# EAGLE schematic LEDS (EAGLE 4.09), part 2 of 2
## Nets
LED2.27: LED0.27.P$A LED1.27.P$A LED2.27.P$A LED3.27.P$A LED4.27.P$A LED5.27.P$A LED6.27.P$A LED7.27.P$A LED8.27.P$A LED9.27.P$A LED10.27.P$A LED11.27.P$A LED12.27.P$A LED13.27.P$A LED14.27.P$A LED15.27.P$A LED16.27.P$A LED17.27.P$A LED18.27.P$A LED19.27.P$A LED20.27.P$A LED21.27.P$A X27.P$
N$X.0: LED0.0.P$A LED1.0.P$A LED2.0.P$A LED3.0.P$A LED4.0.P$A LED5.0.P$A LED6.0.P$A LED7.0.P$A LED8.0.P$A LED9.0.P$A LED10.0.P$A LED11.0.P$A LED12.0.P$A LED13.0.P$A LED14.0.P$A LED15.0.P$A LED16.0.P$A LED17.0.P$A LED18.0.P$A LED19.0.P$A LED20.0.P$A LED21.0.P$A X0.P$
N$X.1: LED0.1.P$A LED1.1.P$A LED2.1.P$A LED3.1.P$A LED4.1.P$A LED5.1.P$A LED6.1.P$A LED7.1.P$A LED8.1.P$A LED9.1.P$A LED10.1.P$A LED11.1.P$A LED12.1.P$A LED13.1.P$A LED14.1.P$A LED15.1.P$A LED16.1.P$A LED17.1.P$A LED18.1.P$A LED19.1.P$A LED20.1.P$A LED21.1.P$A X1.P$
N$X.2: LED0.2.P$A LED1.2.P$A LED2.2.P$A LED3.2.P$A LED4.2.P$A LED5.2.P$A LED6.2.P$A LED7.2.P$A LED8.2.P$A LED9.2.P$A LED10.2.P$A LED11.2.P$A LED12.2.P$A LED13.2.P$A LED14.2.P$A LED15.2.P$A LED16.2.P$A LED17.2.P$A LED18.2.P$A LED19.2.P$A LED20.2.P$A LED21.2.P$A X2.P$
N$X.3: LED0.3.P$A LED1.3.P$A LED2.3.P$A LED3.3.P$A LED4.3.P$A LED5.3.P$A LED6.3.P$A LED7.3.P$A LED8.3.P$A LED9.3.P$A LED10.3.P$A LED11.3.P$A LED12.3.P$A LED13.3.P$A LED14.3.P$A LED15.3.P$A LED16.3.P$A LED17.3.P$A LED18.3.P$A LED19.3.P$A LED20.3.P$A LED21.3.P$A X3.P$
N$X.4: LED0.4.P$A LED1.4.P$A LED2.4.P$A LED3.4.P$A LED4.4.P$A LED5.4.P$A LED6.4.P$A LED7.4.P$A LED8.4.P$A LED9.4.P$A LED10.4.P$A LED11.4.P$A LED12.4.P$A LED13.4.P$A LED14.4.P$A LED15.4.P$A LED16.4.P$A LED17.4.P$A LED18.4.P$A LED19.4.P$A LED20.4.P$A LED21.4.P$A X4.P$
N$X.5: LED0.5.P$A LED1.5.P$A LED2.5.P$A LED3.5.P$A LED4.5.P$A LED5.5.P$A LED6.5.P$A LED7.5.P$A LED8.5.P$A LED9.5.P$A LED10.5.P$A LED11.5.P$A LED12.5.P$A LED13.5.P$A LED14.5.P$A LED15.5.P$A LED16.5.P$A LED17.5.P$A LED18.5.P$A LED19.5.P$A LED20.5.P$A LED21.5.P$A X5.P$
N$X.6: LED0.6.P$A LED1.6.P$A LED2.6.P$A LED3.6.P$A LED4.6.P$A LED5.6.P$A LED6.6.P$A LED7.6.P$A LED8.6.P$A LED9.6.P$A LED10.6.P$A LED11.6.P$A LED12.6.P$A LED13.6.P$A LED14.6.P$A LED15.6.P$A LED16.6.P$A LED17.6.P$A LED18.6.P$A LED19.6.P$A LED20.6.P$A LED21.6.P$A X6.P$
N$X.7: LED0.7.P$A LED1.7.P$A LED2.7.P$A LED3.7.P$A LED4.7.P$A LED5.7.P$A LED6.7.P$A LED7.7.P$A LED8.7.P$A LED9.7.P$A LED10.7.P$A LED11.7.P$A LED12.7.P$A LED13.7.P$A LED14.7.P$A LED15.7.P$A LED16.7.P$A LED17.7.P$A LED18.7.P$A LED19.7.P$A LED20.7.P$A LED21.7.P$A X7.P$
N$X.8: LED0.8.P$A LED1.8.P$A LED2.8.P$A LED3.8.P$A LED4.8.P$A LED5.8.P$A LED6.8.P$A LED7.8.P$A LED8.8.P$A LED9.8.P$A LED10.8.P$A LED11.8.P$A LED12.8.P$A LED13.8.P$A LED14.8.P$A LED15.8.P$A LED16.8.P$A LED17.8.P$A LED18.8.P$A LED19.8.P$A LED20.8.P$A LED21.8.P$A X8.P$
N$X.9: LED0.9.P$A LED1.9.P$A LED2.9.P$A LED3.9.P$A LED4.9.P$A LED5.9.P$A LED6.9.P$A LED7.9.P$A LED8.9.P$A LED9.9.P$A LED10.9.P$A LED11.9.P$A LED12.9.P$A LED13.9.P$A LED14.9.P$A LED15.9.P$A LED16.9.P$A LED17.9.P$A LED18.9.P$A LED19.9.P$A LED20.9.P$A LED21.9.P$A X9.P$
N$X.10: LED0.10.P$A LED1.10.P$A LED2.10.P$A LED3.10.P$A LED4.10.P$A LED5.10.P$A LED6.10.P$A LED7.10.P$A LED8.10.P$A LED9.10.P$A LED10.10.P$A LED11.10.P$A LED12.10.P$A LED13.10.P$A LED14.10.P$A LED15.10.P$A LED16.10.P$A LED17.10.P$A LED18.10.P$A LED19.10.P$A LED20.10.P$A LED21.10.P$A X10.P$
N$X.11: LED0.11.P$A LED1.11.P$A LED2.11.P$A LED3.11.P$A LED4.11.P$A LED5.11.P$A LED6.11.P$A LED7.11.P$A LED8.11.P$A LED9.11.P$A LED10.11.P$A LED11.11.P$A LED12.11.P$A LED13.11.P$A LED14.11.P$A LED15.11.P$A LED16.11.P$A LED17.11.P$A LED18.11.P$A LED19.11.P$A LED20.11.P$A LED21.11.P$A X11.P$
N$X.12: LED0.12.P$A LED1.12.P$A LED2.12.P$A LED3.12.P$A LED4.12.P$A LED5.12.P$A LED6.12.P$A LED7.12.P$A LED8.12.P$A LED9.12.P$A LED10.12.P$A LED11.12.P$A LED12.12.P$A LED13.12.P$A LED14.12.P$A LED15.12.P$A LED16.12.P$A LED17.12.P$A LED18.12.P$A LED19.12.P$A LED20.12.P$A LED21.12.P$A X12.P$
N$X.13: LED0.13.P$A LED1.13.P$A LED2.13.P$A LED3.13.P$A LED4.13.P$A LED5.13.P$A LED6.13.P$A LED7.13.P$A LED8.13.P$A LED9.13.P$A LED10.13.P$A LED11.13.P$A LED12.13.P$A LED13.13.P$A LED14.13.P$A LED15.13.P$A LED16.13.P$A LED17.13.P$A LED18.13.P$A LED19.13.P$A LED20.13.P$A LED21.13.P$A X13.P$
N$X.14: LED0.14.P$A LED1.14.P$A LED2.14.P$A LED3.14.P$A LED4.14.P$A LED5.14.P$A LED6.14.P$A LED7.14.P$A LED8.14.P$A LED9.14.P$A LED10.14.P$A LED11.14.P$A LED12.14.P$A LED13.14.P$A LED14.14.P$A LED15.14.P$A LED16.14.P$A LED17.14.P$A LED18.14.P$A LED19.14.P$A LED20.14.P$A LED21.14.P$A X14.P$
N$X.15: LED0.15.P$A LED1.15.P$A LED2.15.P$A LED3.15.P$A LED4.15.P$A LED5.15.P$A LED6.15.P$A LED7.15.P$A LED8.15.P$A LED9.15.P$A LED10.15.P$A LED11.15.P$A LED12.15.P$A LED13.15.P$A LED14.15.P$A LED15.15.P$A LED16.15.P$A LED17.15.P$A LED18.15.P$A LED19.15.P$A LED20.15.P$A LED21.15.P$A X15.P$
N$X.16: LED0.16.P$A LED1.16.P$A LED2.16.P$A LED3.16.P$A LED4.16.P$A LED5.16.P$A LED6.16.P$A LED7.16.P$A LED8.16.P$A LED9.16.P$A LED10.16.P$A LED11.16.P$A LED12.16.P$A LED13.16.P$A LED14.16.P$A LED15.16.P$A LED16.16.P$A LED17.16.P$A LED18.16.P$A LED19.16.P$A LED20.16.P$A LED21.16.P$A X16.P$
N$X.17: LED0.17.P$A LED1.17.P$A LED2.17.P$A LED3.17.P$A LED4.17.P$A LED5.17.P$A LED6.17.P$A LED7.17.P$A LED8.17.P$A LED9.17.P$A LED10.17.P$A LED11.17.P$A LED12.17.P$A LED13.17.P$A LED14.17.P$A LED15.17.P$A LED16.17.P$A LED17.17.P$A LED18.17.P$A LED19.17.P$A LED20.17.P$A LED21.17.P$A X17.P$
N$X.18: LED0.18.P$A LED1.18.P$A LED2.18.P$A LED3.18.P$A LED4.18.P$A LED5.18.P$A LED6.18.P$A LED7.18.P$A LED8.18.P$A LED9.18.P$A LED10.18.P$A LED11.18.P$A LED12.18.P$A LED13.18.P$A LED14.18.P$A LED15.18.P$A LED16.18.P$A LED17.18.P$A LED18.18.P$A LED19.18.P$A LED20.18.P$A LED21.18.P$A X18.P$
N$X.19: LED0.19.P$A LED1.19.P$A LED2.19.P$A LED3.19.P$A LED4.19.P$A LED5.19.P$A LED6.19.P$A LED7.19.P$A LED8.19.P$A LED9.19.P$A LED10.19.P$A LED11.19.P$A LED12.19.P$A LED13.19.P$A LED14.19.P$A LED15.19.P$A LED16.19.P$A LED17.19.P$A LED18.19.P$A LED19.19.P$A LED20.19.P$A LED21.19.P$A X19.P$
N$X.20: LED0.20.P$A LED1.20.P$A LED2.20.P$A LED3.20.P$A LED4.20.P$A LED5.20.P$A LED6.20.P$A LED7.20.P$A LED8.20.P$A LED9.20.P$A LED10.20.P$A LED11.20.P$A LED12.20.P$A LED13.20.P$A LED14.20.P$A LED15.20.P$A LED16.20.P$A LED17.20.P$A LED18.20.P$A LED19.20.P$A LED20.20.P$A LED21.20.P$A X20.P$
N$X.21: LED0.21.P$A LED1.21.P$A LED2.21.P$A LED3.21.P$A LED4.21.P$A LED5.21.P$A LED6.21.P$A LED7.21.P$A LED8.21.P$A LED9.21.P$A LED10.21.P$A LED11.21.P$A LED12.21.P$A LED13.21.P$A LED14.21.P$A LED15.21.P$A LED16.21.P$A LED17.21.P$A LED18.21.P$A LED19.21.P$A LED20.21.P$A LED21.21.P$A X21.P$
N$X.22: LED0.22.P$A LED1.22.P$A LED2.22.P$A LED3.22.P$A LED4.22.P$A LED5.22.P$A LED6.22.P$A LED7.22.P$A LED8.22.P$A LED9.22.P$A LED10.22.P$A LED11.22.P$A LED12.22.P$A LED13.22.P$A LED14.22.P$A LED15.22.P$A LED16.22.P$A LED17.22.P$A LED18.22.P$A LED19.22.P$A LED20.22.P$A LED21.22.P$A X22.P$
N$X.23: LED0.23.P$A LED1.23.P$A LED2.23.P$A LED3.23.P$A LED4.23.P$A LED5.23.P$A LED6.23.P$A LED7.23.P$A LED8.23.P$A LED9.23.P$A LED10.23.P$A LED11.23.P$A LED12.23.P$A LED13.23.P$A LED14.23.P$A LED15.23.P$A LED16.23.P$A LED17.23.P$A LED18.23.P$A LED19.23.P$A LED20.23.P$A LED21.23.P$A X23.P$
N$X.24: LED0.24.P$A LED1.24.P$A LED2.24.P$A LED3.24.P$A LED4.24.P$A LED5.24.P$A LED6.24.P$A LED7.24.P$A LED8.24.P$A LED9.24.P$A LED10.24.P$A LED11.24.P$A LED12.24.P$A LED13.24.P$A LED14.24.P$A LED15.24.P$A LED16.24.P$A LED17.24.P$A LED18.24.P$A LED19.24.P$A LED20.24.P$A LED21.24.P$A X24.P$
N$X.25: LED0.25.P$A LED1.25.P$A LED2.25.P$A LED3.25.P$A LED4.25.P$A LED5.25.P$A LED6.25.P$A LED7.25.P$A LED8.25.P$A LED9.25.P$A LED10.25.P$A LED11.25.P$A LED12.25.P$A LED13.25.P$A LED14.25.P$A LED15.25.P$A LED16.25.P$A LED17.25.P$A LED18.25.P$A LED19.25.P$A LED20.25.P$A LED21.25.P$A X25.P$
N$X.26: LED0.26.P$A LED1.26.P$A LED2.26.P$A LED3.26.P$A LED4.26.P$A LED5.26.P$A LED6.26.P$A LED7.26.P$A LED8.26.P$A LED9.26.P$A LED10.26.P$A LED11.26.P$A LED12.26.P$A LED13.26.P$A LED14.26.P$A LED15.26.P$A LED16.26.P$A LED17.26.P$A LED18.26.P$A LED19.26.P$A LED20.26.P$A LED21.26.P$A X26.P$
N$X.28: LED0.28.P$A LED1.28.P$A LED2.28.P$A LED3.28.P$A LED4.28.P$A LED5.28.P$A LED6.28.P$A LED7.28.P$A LED8.28.P$A LED9.28.P$A LED10.28.P$A LED11.28.P$A LED12.28.P$A LED13.28.P$A LED14.28.P$A LED15.28.P$A LED16.28.P$A LED17.28.P$A LED18.28.P$A LED19.28.P$A LED20.28.P$A LED21.28.P$A X28.P$
N$X.29: LED0.29.P$A LED1.29.P$A LED2.29.P$A LED3.29.P$A LED4.29.P$A LED5.29.P$A LED6.29.P$A LED7.29.P$A LED8.29.P$A LED9.29.P$A LED10.29.P$A LED11.29.P$A LED12.29.P$A LED13.29.P$A LED14.29.P$A LED15.29.P$A LED16.29.P$A LED17.29.P$A LED18.29.P$A LED19.29.P$A LED20.29.P$A LED21.29.P$A X29.P$
N$X.30: LED0.30.P$A LED1.30.P$A LED2.30.P$A LED3.30.P$A LED4.30.P$A LED5.30.P$A LED6.30.P$A LED7.30.P$A LED8.30.P$A LED9.30.P$A LED10.30.P$A LED11.30.P$A LED12.30.P$A LED13.30.P$A LED14.30.P$A LED15.30.P$A LED16.30.P$A LED17.30.P$A LED18.30.P$A LED19.30.P$A LED20.30.P$A LED21.30.P$A X30.P$
N$X.31: LED0.31.P$A LED1.31.P$A LED2.31.P$A LED3.31.P$A LED4.31.P$A LED5.31.P$A LED6.31.P$A LED7.31.P$A LED8.31.P$A LED9.31.P$A LED10.31.P$A LED11.31.P$A LED12.31.P$A LED13.31.P$A LED14.31.P$A LED15.31.P$A LED16.31.P$A LED17.31.P$A LED18.31.P$A LED19.31.P$A LED20.31.P$A LED21.31.P$A X31.P$
N$X.32: LED0.32.P$A LED1.32.P$A LED2.32.P$A LED3.32.P$A LED4.32.P$A LED5.32.P$A LED6.32.P$A LED7.32.P$A LED8.32.P$A LED9.32.P$A LED10.32.P$A LED11.32.P$A LED12.32.P$A LED13.32.P$A LED14.32.P$A LED15.32.P$A LED16.32.P$A LED17.32.P$A LED18.32.P$A LED19.32.P$A LED20.32.P$A LED21.32.P$A X32.P$
N$X.33: LED0.33.P$A LED1.33.P$A LED2.33.P$A LED3.33.P$A LED4.33.P$A LED5.33.P$A LED6.33.P$A LED7.33.P$A LED8.33.P$A LED9.33.P$A LED10.33.P$A LED11.33.P$A LED12.33.P$A LED13.33.P$A LED14.33.P$A LED15.33.P$A LED16.33.P$A LED17.33.P$A LED18.33.P$A LED19.33.P$A LED20.33.P$A LED21.33.P$A X33.P$
N$X.34: LED0.34.P$A LED1.34.P$A LED2.34.P$A LED3.34.P$A LED4.34.P$A LED5.34.P$A LED6.34.P$A LED7.34.P$A LED8.34.P$A LED9.34.P$A LED10.34.P$A LED11.34.P$A LED12.34.P$A LED13.34.P$A LED14.34.P$A LED15.34.P$A LED16.34.P$A LED17.34.P$A LED18.34.P$A LED19.34.P$A LED20.34.P$A LED21.34.P$A X34.P$
N$X.35: LED0.35.P$A LED1.35.P$A LED2.35.P$A LED3.35.P$A LED4.35.P$A LED5.35.P$A LED6.35.P$A LED7.35.P$A LED8.35.P$A LED9.35.P$A LED10.35.P$A LED11.35.P$A LED12.35.P$A LED13.35.P$A LED14.35.P$A LED15.35.P$A LED16.35.P$A LED17.35.P$A LED18.35.P$A LED19.35.P$A LED20.35.P$A LED21.35.P$A X35.P$
N$X.36: LED0.36.P$A LED1.36.P$A LED2.36.P$A LED3.36.P$A LED4.36.P$A LED5.36.P$A LED6.36.P$A LED7.36.P$A LED8.36.P$A LED9.36.P$A LED10.36.P$A LED11.36.P$A LED12.36.P$A LED13.36.P$A LED14.36.P$A LED15.36.P$A LED16.36.P$A LED17.36.P$A LED18.36.P$A LED19.36.P$A LED20.36.P$A LED21.36.P$A X36.P$
N$X.37: LED0.37.P$A LED1.37.P$A LED2.37.P$A LED3.37.P$A LED4.37.P$A LED5.37.P$A LED6.37.P$A LED7.37.P$A LED8.37.P$A LED9.37.P$A LED10.37.P$A LED11.37.P$A LED12.37.P$A LED13.37.P$A LED14.37.P$A LED15.37.P$A LED16.37.P$A LED17.37.P$A LED18.37.P$A LED19.37.P$A LED20.37.P$A LED21.37.P$A X37.P$
N$X.38: LED0.38.P$A LED1.38.P$A LED2.38.P$A LED3.38.P$A LED4.38.P$A LED5.38.P$A LED6.38.P$A LED7.38.P$A LED8.38.P$A LED9.38.P$A LED10.38.P$A LED11.38.P$A LED12.38.P$A LED13.38.P$A LED14.38.P$A LED15.38.P$A LED16.38.P$A LED17.38.P$A LED18.38.P$A LED19.38.P$A LED20.38.P$A LED21.38.P$A X38.P$
N$X.39: LED0.39.P$A LED1.39.P$A LED2.39.P$A LED3.39.P$A LED4.39.P$A LED5.39.P$A LED6.39.P$A LED7.39.P$A LED8.39.P$A LED9.39.P$A LED10.39.P$A LED11.39.P$A LED12.39.P$A LED13.39.P$A LED14.39.P$A LED15.39.P$A LED16.39.P$A LED17.39.P$A LED18.39.P$A LED19.39.P$A LED20.39.P$A LED21.39.P$A X39.P$
N$X.40: LED0.40.P$A LED1.40.P$A LED2.40.P$A LED3.40.P$A LED4.40.P$A LED5.40.P$A LED6.40.P$A LED7.40.P$A LED8.40.P$A LED9.40.P$A LED10.40.P$A LED11.40.P$A LED12.40.P$A LED13.40.P$A LED14.40.P$A LED15.40.P$A LED16.40.P$A LED17.40.P$A LED18.40.P$A LED19.40.P$A LED20.40.P$A LED21.40.P$A X40.P$
N$X.41: LED0.41.P$A LED1.41.P$A LED2.41.P$A LED3.41.P$A LED4.41.P$A LED5.41.P$A LED6.41.P$A LED7.41.P$A LED8.41.P$A LED9.41.P$A LED10.41.P$A LED11.41.P$A LED12.41.P$A LED13.41.P$A LED14.41.P$A LED15.41.P$A LED16.41.P$A LED17.41.P$A LED18.41.P$A LED19.41.P$A LED20.41.P$A LED21.41.P$A X41.P$
N$X.42: LED0.42.P$A LED1.42.P$A LED2.42.P$A LED3.42.P$A LED4.42.P$A LED5.42.P$A LED6.42.P$A LED7.42.P$A LED8.42.P$A LED9.42.P$A LED10.42.P$A LED11.42.P$A LED12.42.P$A LED13.42.P$A LED14.42.P$A LED15.42.P$A LED16.42.P$A LED17.42.P$A LED18.42.P$A LED19.42.P$A LED20.42.P$A LED21.42.P$A X42.P$
N$X.43: LED0.43.P$A LED1.43.P$A LED2.43.P$A LED3.43.P$A LED4.43.P$A LED5.43.P$A LED6.43.P$A LED7.43.P$A LED8.43.P$A LED9.43.P$A LED10.43.P$A LED11.43.P$A LED12.43.P$A LED13.43.P$A LED14.43.P$A LED15.43.P$A LED16.43.P$A LED17.43.P$A LED18.43.P$A LED19.43.P$A LED20.43.P$A LED21.43.P$A X43.P$
N$X.44: LED0.44.P$A LED1.44.P$A LED2.44.P$A LED3.44.P$A LED4.44.P$A LED5.44.P$A LED6.44.P$A LED7.44.P$A LED8.44.P$A LED9.44.P$A LED10.44.P$A LED11.44.P$A LED12.44.P$A LED13.44.P$A LED14.44.P$A LED15.44.P$A LED16.44.P$A LED17.44.P$A LED18.44.P$A LED19.44.P$A LED20.44.P$A LED21.44.P$A X44.P$
N$X.45: LED0.45.P$A LED1.45.P$A LED2.45.P$A LED3.45.P$A LED4.45.P$A LED5.45.P$A LED6.45.P$A LED7.45.P$A LED8.45.P$A LED9.45.P$A LED10.45.P$A LED11.45.P$A LED12.45.P$A LED13.45.P$A LED14.45.P$A LED15.45.P$A LED16.45.P$A LED17.45.P$A LED18.45.P$A LED19.45.P$A LED20.45.P$A LED21.45.P$A X45.P$
N$X.46: LED0.46.P$A LED1.46.P$A LED2.46.P$A LED3.46.P$A LED4.46.P$A LED5.46.P$A LED6.46.P$A LED7.46.P$A LED8.46.P$A LED9.46.P$A LED10.46.P$A LED11.46.P$A LED12.46.P$A LED13.46.P$A LED14.46.P$A LED15.46.P$A LED16.46.P$A LED17.46.P$A LED18.46.P$A LED19.46.P$A LED20.46.P$A LED21.46.P$A X46.P$
N$X.47: LED0.47.P$A LED1.47.P$A LED2.47.P$A LED3.47.P$A LED4.47.P$A LED5.47.P$A LED6.47.P$A LED7.47.P$A LED8.47.P$A LED9.47.P$A LED10.47.P$A LED11.47.P$A LED12.47.P$A LED13.47.P$A LED14.47.P$A LED15.47.P$A LED16.47.P$A LED17.47.P$A LED18.47.P$A LED19.47.P$A LED20.47.P$A LED21.47.P$A X47.P$
N$X.48: LED0.48.P$A LED1.48.P$A LED2.48.P$A LED3.48.P$A LED4.48.P$A LED5.48.P$A LED6.48.P$A LED7.48.P$A LED8.48.P$A LED9.48.P$A LED10.48.P$A LED11.48.P$A LED12.48.P$A LED13.48.P$A LED14.48.P$A LED15.48.P$A LED16.48.P$A LED17.48.P$A LED18.48.P$A LED19.48.P$A LED20.48.P$A LED21.48.P$A X48.P$
N$X.49: LED0.49.P$A LED1.49.P$A LED2.49.P$A LED3.49.P$A LED4.49.P$A LED5.49.P$A LED6.49.P$A LED7.49.P$A LED8.49.P$A LED9.49.P$A LED10.49.P$A LED11.49.P$A LED12.49.P$A LED13.49.P$A LED14.49.P$A LED15.49.P$A LED16.49.P$A LED17.49.P$A LED18.49.P$A LED19.49.P$A LED20.49.P$A LED21.49.P$A X49.P$
N$X.50: LED0.50.P$A LED1.50.P$A LED2.50.P$A LED3.50.P$A LED4.50.P$A LED5.50.P$A LED6.50.P$A LED7.50.P$A LED8.50.P$A LED9.50.P$A LED10.50.P$A LED11.50.P$A LED12.50.P$A LED13.50.P$A LED14.50.P$A LED15.50.P$A LED16.50.P$A LED17.50.P$A LED18.50.P$A LED19.50.P$A LED20.50.P$A LED21.50.P$A X50.P$
N$X.51: LED0.51.P$A LED1.51.P$A LED2.51.P$A LED3.51.P$A LED4.51.P$A LED5.51.P$A LED6.51.P$A LED7.51.P$A LED8.51.P$A LED9.51.P$A LED10.51.P$A LED11.51.P$A LED12.51.P$A LED13.51.P$A LED14.51.P$A LED15.51.P$A LED16.51.P$A LED17.51.P$A LED18.51.P$A LED19.51.P$A LED20.51.P$A LED21.51.P$A X51.P$
N$X.52: LED0.52.P$A LED1.52.P$A LED2.52.P$A LED3.52.P$A LED4.52.P$A LED5.52.P$A LED6.52.P$A LED7.52.P$A LED8.52.P$A LED9.52.P$A LED10.52.P$A LED11.52.P$A LED12.52.P$A LED13.52.P$A LED14.52.P$A LED15.52.P$A LED16.52.P$A LED17.52.P$A LED18.52.P$A LED19.52.P$A LED20.52.P$A LED21.52.P$A X52.P$
N$X.53: LED0.53.P$A LED1.53.P$A LED2.53.P$A LED3.53.P$A LED4.53.P$A LED5.53.P$A LED6.53.P$A LED7.53.P$A LED8.53.P$A LED9.53.P$A LED10.53.P$A LED11.53.P$A LED12.53.P$A LED13.53.P$A LED14.53.P$A LED15.53.P$A LED16.53.P$A LED17.53.P$A LED18.53.P$A LED19.53.P$A LED20.53.P$A LED21.53.P$A X53.P$
N$X.54: LED0.54.P$A LED1.54.P$A LED2.54.P$A LED3.54.P$A LED4.54.P$A LED5.54.P$A LED6.54.P$A LED7.54.P$A LED8.54.P$A LED9.54.P$A LED10.54.P$A LED11.54.P$A LED12.54.P$A LED13.54.P$A LED14.54.P$A LED15.54.P$A LED16.54.P$A LED17.54.P$A LED18.54.P$A LED19.54.P$A LED20.54.P$A LED21.54.P$A X54.P$
N$X.55: LED0.55.P$A LED1.55.P$A LED2.55.P$A LED3.55.P$A LED4.55.P$A LED5.55.P$A LED6.55.P$A LED7.55.P$A LED8.55.P$A LED9.55.P$A LED10.55.P$A LED11.55.P$A LED12.55.P$A LED13.55.P$A LED14.55.P$A LED15.55.P$A LED16.55.P$A LED17.55.P$A LED18.55.P$A LED19.55.P$A LED20.55.P$A LED21.55.P$A X55.P$
N$X.56: LED0.56.P$A LED1.56.P$A LED2.56.P$A LED3.56.P$A LED4.56.P$A LED5.56.P$A LED6.56.P$A LED7.56.P$A LED8.56.P$A LED9.56.P$A LED10.56.P$A LED11.56.P$A LED12.56.P$A LED13.56.P$A LED14.56.P$A LED15.56.P$A LED16.56.P$A LED17.56.P$A LED18.56.P$A LED19.56.P$A LED20.56.P$A LED21.56.P$A X56.P$
N$X.57: LED0.57.P$A LED1.57.P$A LED2.57.P$A LED3.57.P$A LED4.57.P$A LED5.57.P$A LED6.57.P$A LED7.57.P$A LED8.57.P$A LED9.57.P$A LED10.57.P$A LED11.57.P$A LED12.57.P$A LED13.57.P$A LED14.57.P$A LED15.57.P$A LED16.57.P$A LED17.57.P$A LED18.57.P$A LED19.57.P$A LED20.57.P$A LED21.57.P$A X57.P$
N$X.58: LED0.58.P$A LED1.58.P$A LED2.58.P$A LED3.58.P$A LED4.58.P$A LED5.58.P$A LED6.58.P$A LED7.58.P$A LED8.58.P$A LED9.58.P$A LED10.58.P$A LED11.58.P$A LED12.58.P$A LED13.58.P$A LED14.58.P$A LED15.58.P$A LED16.58.P$A LED17.58.P$A LED18.58.P$A LED19.58.P$A LED20.58.P$A LED21.58.P$A X58.P$
N$X.59: LED0.59.P$A LED1.59.P$A LED2.59.P$A LED3.59.P$A LED4.59.P$A LED5.59.P$A LED6.59.P$A LED7.59.P$A LED8.59.P$A LED9.59.P$A LED10.59.P$A LED11.59.P$A LED12.59.P$A LED13.59.P$A LED14.59.P$A LED15.59.P$A LED16.59.P$A LED17.59.P$A LED18.59.P$A LED19.59.P$A LED20.59.P$A LED21.59.P$A X59.P$
N$X.60: LED0.60.P$A LED1.60.P$A LED2.60.P$A LED3.60.P$A LED4.60.P$A LED5.60.P$A LED6.60.P$A LED7.60.P$A LED8.60.P$A LED9.60.P$A LED10.60.P$A LED11.60.P$A LED12.60.P$A LED13.60.P$A LED14.60.P$A LED15.60.P$A LED16.60.P$A LED17.60.P$A LED18.60.P$A LED19.60.P$A LED20.60.P$A LED21.60.P$A X60.P$
N$X.61: LED0.61.P$A LED1.61.P$A LED2.61.P$A LED3.61.P$A LED4.61.P$A LED5.61.P$A LED6.61.P$A LED7.61.P$A LED8.61.P$A LED9.61.P$A LED10.61.P$A LED11.61.P$A LED12.61.P$A LED13.61.P$A LED14.61.P$A LED15.61.P$A LED16.61.P$A LED17.61.P$A LED18.61.P$A LED19.61.P$A LED20.61.P$A LED21.61.P$A X61.P$
N$X.62: LED0.62.P$A LED1.62.P$A LED2.62.P$A LED3.62.P$A LED4.62.P$A LED5.62.P$A LED6.62.P$A LED7.62.P$A LED8.62.P$A LED9.62.P$A LED10.62.P$A LED11.62.P$A LED12.62.P$A LED13.62.P$A LED14.62.P$A LED15.62.P$A LED16.62.P$A LED17.62.P$A LED18.62.P$A LED19.62.P$A LED20.62.P$A LED21.62.P$A X62.P$
N$X.63: LED0.63.P$A LED1.63.P$A LED2.63.P$A LED3.63.P$A LED4.63.P$A LED5.63.P$A LED6.63.P$A LED7.63.P$A LED8.63.P$A LED9.63.P$A LED10.63.P$A LED11.63.P$A LED12.63.P$A LED13.63.P$A LED14.63.P$A LED15.63.P$A LED16.63.P$A LED17.63.P$A LED18.63.P$A LED19.63.P$A LED20.63.P$A LED21.63.P$A X63.P$
N$Y.0: LED0.0.P$K LED0.1.P$K LED0.2.P$K LED0.3.P$K LED0.4.P$K LED0.5.P$K LED0.6.P$K LED0.7.P$K LED0.8.P$K LED0.9.P$K LED0.10.P$K LED0.11.P$K LED0.12.P$K LED0.13.P$K LED0.14.P$K LED0.15.P$K LED0.16.P$K LED0.17.P$K LED0.18.P$K LED0.19.P$K LED0.20.P$K LED0.21.P$K LED0.22.P$K LED0.23.P$K LED0.24.P$K LED0.25.P$K LED0.26.P$K LED0.27.P$K LED0.28.P$K LED0.29.P$K LED0.30.P$K LED0.31.P$K LED0.32.P$K LED0.33.P$K LED0.34.P$K LED0.35.P$K LED0.36.P$K LED0.37.P$K LED0.38.P$K LED0.39.P$K LED0.40.P$K LED0.41.P$K LED0.42.P$K LED0.43.P$K LED0.44.P$K LED0.45.P$K LED0.46.P$K LED0.47.P$K LED0.48.P$K LED0.49.P$K LED0.50.P$K LED0.51.P$K LED0.52.P$K LED0.53.P$K LED0.54.P$K LED0.55.P$K LED0.56.P$K LED0.57.P$K LED0.58.P$K LED0.59.P$K LED0.60.P$K LED0.61.P$K LED0.62.P$K LED0.63.P$K Y.0.P$
N$Y.1: LED1.0.P$K LED1.1.P$K LED1.2.P$K LED1.3.P$K LED1.4.P$K LED1.5.P$K LED1.6.P$K LED1.7.P$K LED1.8.P$K LED1.9.P$K LED1.10.P$K LED1.11.P$K LED1.12.P$K LED1.13.P$K LED1.14.P$K LED1.15.P$K LED1.16.P$K LED1.17.P$K LED1.18.P$K LED1.19.P$K LED1.20.P$K LED1.21.P$K LED1.22.P$K LED1.23.P$K LED1.24.P$K LED1.25.P$K LED1.26.P$K LED1.27.P$K LED1.28.P$K LED1.29.P$K LED1.30.P$K LED1.31.P$K LED1.32.P$K LED1.33.P$K LED1.34.P$K LED1.35.P$K LED1.36.P$K LED1.37.P$K LED1.38.P$K LED1.39.P$K LED1.40.P$K LED1.41.P$K LED1.42.P$K LED1.43.P$K LED1.44.P$K LED1.45.P$K LED1.46.P$K LED1.47.P$K LED1.48.P$K LED1.49.P$K LED1.50.P$K LED1.51.P$K LED1.52.P$K LED1.53.P$K LED1.54.P$K LED1.55.P$K LED1.56.P$K LED1.57.P$K LED1.58.P$K LED1.59.P$K LED1.60.P$K LED1.61.P$K LED1.62.P$K LED1.63.P$K Y.1.P$
N$Y.2: LED2.0.P$K LED2.1.P$K LED2.2.P$K LED2.3.P$K LED2.4.P$K LED2.5.P$K LED2.6.P$K LED2.7.P$K LED2.8.P$K LED2.9.P$K LED2.10.P$K LED2.11.P$K LED2.12.P$K LED2.13.P$K LED2.14.P$K LED2.15.P$K LED2.16.P$K LED2.17.P$K LED2.18.P$K LED2.19.P$K LED2.20.P$K LED2.21.P$K LED2.22.P$K LED2.23.P$K LED2.24.P$K LED2.25.P$K LED2.26.P$K LED2.27.P$K LED2.28.P$K LED2.29.P$K LED2.30.P$K LED2.31.P$K LED2.32.P$K LED2.33.P$K LED2.34.P$K LED2.35.P$K LED2.36.P$K LED2.37.P$K LED2.38.P$K LED2.39.P$K LED2.40.P$K LED2.41.P$K LED2.42.P$K LED2.43.P$K LED2.44.P$K LED2.45.P$K LED2.46.P$K LED2.47.P$K LED2.48.P$K LED2.49.P$K LED2.50.P$K LED2.51.P$K LED2.52.P$K LED2.53.P$K LED2.54.P$K LED2.55.P$K LED2.56.P$K LED2.57.P$K LED2.58.P$K LED2.59.P$K LED2.60.P$K LED2.61.P$K LED2.62.P$K LED2.63.P$K Y.2.P$
N$Y.3: LED3.0.P$K LED3.1.P$K LED3.2.P$K LED3.3.P$K LED3.4.P$K LED3.5.P$K LED3.6.P$K LED3.7.P$K LED3.8.P$K LED3.9.P$K LED3.10.P$K LED3.11.P$K LED3.12.P$K LED3.13.P$K LED3.14.P$K LED3.15.P$K LED3.16.P$K LED3.17.P$K LED3.18.P$K LED3.19.P$K LED3.20.P$K LED3.21.P$K LED3.22.P$K LED3.23.P$K LED3.24.P$K LED3.25.P$K LED3.26.P$K LED3.27.P$K LED3.28.P$K LED3.29.P$K LED3.30.P$K LED3.31.P$K LED3.32.P$K LED3.33.P$K LED3.34.P$K LED3.35.P$K LED3.36.P$K LED3.37.P$K LED3.38.P$K LED3.39.P$K LED3.40.P$K LED3.41.P$K LED3.42.P$K LED3.43.P$K LED3.44.P$K LED3.45.P$K LED3.46.P$K LED3.47.P$K LED3.48.P$K LED3.49.P$K LED3.50.P$K LED3.51.P$K LED3.52.P$K LED3.53.P$K LED3.54.P$K LED3.55.P$K LED3.56.P$K LED3.57.P$K LED3.58.P$K LED3.59.P$K LED3.60.P$K LED3.61.P$K LED3.62.P$K LED3.63.P$K Y.3.P$
N$Y.4: LED4.0.P$K LED4.1.P$K LED4.2.P$K LED4.3.P$K LED4.4.P$K LED4.5.P$K LED4.6.P$K LED4.7.P$K LED4.8.P$K LED4.9.P$K LED4.10.P$K LED4.11.P$K LED4.12.P$K LED4.13.P$K LED4.14.P$K LED4.15.P$K LED4.16.P$K LED4.17.P$K LED4.18.P$K LED4.19.P$K LED4.20.P$K LED4.21.P$K LED4.22.P$K LED4.23.P$K LED4.24.P$K LED4.25.P$K LED4.26.P$K LED4.27.P$K LED4.28.P$K LED4.29.P$K LED4.30.P$K LED4.31.P$K LED4.32.P$K LED4.33.P$K LED4.34.P$K LED4.35.P$K LED4.36.P$K LED4.37.P$K LED4.38.P$K LED4.39.P$K LED4.40.P$K LED4.41.P$K LED4.42.P$K LED4.43.P$K LED4.44.P$K LED4.45.P$K LED4.46.P$K LED4.47.P$K LED4.48.P$K LED4.49.P$K LED4.50.P$K LED4.51.P$K LED4.52.P$K LED4.53.P$K LED4.54.P$K LED4.55.P$K LED4.56.P$K LED4.57.P$K LED4.58.P$K LED4.59.P$K LED4.60.P$K LED4.61.P$K LED4.62.P$K LED4.63.P$K Y.4.P$
N$Y.5: LED5.0.P$K LED5.1.P$K LED5.2.P$K LED5.3.P$K LED5.4.P$K LED5.5.P$K LED5.6.P$K LED5.7.P$K LED5.8.P$K LED5.9.P$K LED5.10.P$K LED5.11.P$K LED5.12.P$K LED5.13.P$K LED5.14.P$K LED5.15.P$K LED5.16.P$K LED5.17.P$K LED5.18.P$K LED5.19.P$K LED5.20.P$K LED5.21.P$K LED5.22.P$K LED5.23.P$K LED5.24.P$K LED5.25.P$K LED5.26.P$K LED5.27.P$K LED5.28.P$K LED5.29.P$K LED5.30.P$K LED5.31.P$K LED5.32.P$K LED5.33.P$K LED5.34.P$K LED5.35.P$K LED5.36.P$K LED5.37.P$K LED5.38.P$K LED5.39.P$K LED5.40.P$K LED5.41.P$K LED5.42.P$K LED5.43.P$K LED5.44.P$K LED5.45.P$K LED5.46.P$K LED5.47.P$K LED5.48.P$K LED5.49.P$K LED5.50.P$K LED5.51.P$K LED5.52.P$K LED5.53.P$K LED5.54.P$K LED5.55.P$K LED5.56.P$K LED5.57.P$K LED5.58.P$K LED5.59.P$K LED5.60.P$K LED5.61.P$K LED5.62.P$K LED5.63.P$K Y.5.P$
N$Y.6: LED6.0.P$K LED6.1.P$K LED6.2.P$K LED6.3.P$K LED6.4.P$K LED6.5.P$K LED6.6.P$K LED6.7.P$K LED6.8.P$K LED6.9.P$K LED6.10.P$K LED6.11.P$K LED6.12.P$K LED6.13.P$K LED6.14.P$K LED6.15.P$K LED6.16.P$K LED6.17.P$K LED6.18.P$K LED6.19.P$K LED6.20.P$K LED6.21.P$K LED6.22.P$K LED6.23.P$K LED6.24.P$K LED6.25.P$K LED6.26.P$K LED6.27.P$K LED6.28.P$K LED6.29.P$K LED6.30.P$K LED6.31.P$K LED6.32.P$K LED6.33.P$K LED6.34.P$K LED6.35.P$K LED6.36.P$K LED6.37.P$K LED6.38.P$K LED6.39.P$K LED6.40.P$K LED6.41.P$K LED6.42.P$K LED6.43.P$K LED6.44.P$K LED6.45.P$K LED6.46.P$K LED6.47.P$K LED6.48.P$K LED6.49.P$K LED6.50.P$K LED6.51.P$K LED6.52.P$K LED6.53.P$K LED6.54.P$K LED6.55.P$K LED6.56.P$K LED6.57.P$K LED6.58.P$K LED6.59.P$K LED6.60.P$K LED6.61.P$K LED6.62.P$K LED6.63.P$K Y.6.P$
N$Y.7: LED7.0.P$K LED7.1.P$K LED7.2.P$K LED7.3.P$K LED7.4.P$K LED7.5.P$K LED7.6.P$K LED7.7.P$K LED7.8.P$K LED7.9.P$K LED7.10.P$K LED7.11.P$K LED7.12.P$K LED7.13.P$K LED7.14.P$K LED7.15.P$K LED7.16.P$K LED7.17.P$K LED7.18.P$K LED7.19.P$K LED7.20.P$K LED7.21.P$K LED7.22.P$K LED7.23.P$K LED7.24.P$K LED7.25.P$K LED7.26.P$K LED7.27.P$K LED7.28.P$K LED7.29.P$K LED7.30.P$K LED7.31.P$K LED7.32.P$K LED7.33.P$K LED7.34.P$K LED7.35.P$K LED7.36.P$K LED7.37.P$K LED7.38.P$K LED7.39.P$K LED7.40.P$K LED7.41.P$K LED7.42.P$K LED7.43.P$K LED7.44.P$K LED7.45.P$K LED7.46.P$K LED7.47.P$K LED7.48.P$K LED7.49.P$K LED7.50.P$K LED7.51.P$K LED7.52.P$K LED7.53.P$K LED7.54.P$K LED7.55.P$K LED7.56.P$K LED7.57.P$K LED7.58.P$K LED7.59.P$K LED7.60.P$K LED7.61.P$K LED7.62.P$K LED7.63.P$K Y.7.P$
N$Y.8: LED8.0.P$K LED8.1.P$K LED8.2.P$K LED8.3.P$K LED8.4.P$K LED8.5.P$K LED8.6.P$K LED8.7.P$K LED8.8.P$K LED8.9.P$K LED8.10.P$K LED8.11.P$K LED8.12.P$K LED8.13.P$K LED8.14.P$K LED8.15.P$K LED8.16.P$K LED8.17.P$K LED8.18.P$K LED8.19.P$K LED8.20.P$K LED8.21.P$K LED8.22.P$K LED8.23.P$K LED8.24.P$K LED8.25.P$K LED8.26.P$K LED8.27.P$K LED8.28.P$K LED8.29.P$K LED8.30.P$K LED8.31.P$K LED8.32.P$K LED8.33.P$K LED8.34.P$K LED8.35.P$K LED8.36.P$K LED8.37.P$K LED8.38.P$K LED8.39.P$K LED8.40.P$K LED8.41.P$K LED8.42.P$K LED8.43.P$K LED8.44.P$K LED8.45.P$K LED8.46.P$K LED8.47.P$K LED8.48.P$K LED8.49.P$K LED8.50.P$K LED8.51.P$K LED8.52.P$K LED8.53.P$K LED8.54.P$K LED8.55.P$K LED8.56.P$K LED8.57.P$K LED8.58.P$K LED8.59.P$K LED8.60.P$K LED8.61.P$K LED8.62.P$K LED8.63.P$K Y.8.P$
N$Y.9: LED9.0.P$K LED9.1.P$K LED9.2.P$K LED9.3.P$K LED9.4.P$K LED9.5.P$K LED9.6.P$K LED9.7.P$K LED9.8.P$K LED9.9.P$K LED9.10.P$K LED9.11.P$K LED9.12.P$K LED9.13.P$K LED9.14.P$K LED9.15.P$K LED9.16.P$K LED9.17.P$K LED9.18.P$K LED9.19.P$K LED9.20.P$K LED9.21.P$K LED9.22.P$K LED9.23.P$K LED9.24.P$K LED9.25.P$K LED9.26.P$K LED9.27.P$K LED9.28.P$K LED9.29.P$K LED9.30.P$K LED9.31.P$K LED9.32.P$K LED9.33.P$K LED9.34.P$K LED9.35.P$K LED9.36.P$K LED9.37.P$K LED9.38.P$K LED9.39.P$K LED9.40.P$K LED9.41.P$K LED9.42.P$K LED9.43.P$K LED9.44.P$K LED9.45.P$K LED9.46.P$K LED9.47.P$K LED9.48.P$K LED9.49.P$K LED9.50.P$K LED9.51.P$K LED9.52.P$K LED9.53.P$K LED9.54.P$K LED9.55.P$K LED9.56.P$K LED9.57.P$K LED9.58.P$K LED9.59.P$K LED9.60.P$K LED9.61.P$K LED9.62.P$K LED9.63.P$K Y.9.P$
N$Y.10: LED10.0.P$K LED10.1.P$K LED10.2.P$K LED10.3.P$K LED10.4.P$K LED10.5.P$K LED10.6.P$K LED10.7.P$K LED10.8.P$K LED10.9.P$K LED10.10.P$K LED10.11.P$K LED10.12.P$K LED10.13.P$K LED10.14.P$K LED10.15.P$K LED10.16.P$K LED10.17.P$K LED10.18.P$K LED10.19.P$K LED10.20.P$K LED10.21.P$K LED10.22.P$K LED10.23.P$K LED10.24.P$K LED10.25.P$K LED10.26.P$K LED10.27.P$K LED10.28.P$K LED10.29.P$K LED10.30.P$K LED10.31.P$K LED10.32.P$K LED10.33.P$K LED10.34.P$K LED10.35.P$K LED10.36.P$K LED10.37.P$K LED10.38.P$K LED10.39.P$K LED10.40.P$K LED10.41.P$K LED10.42.P$K LED10.43.P$K LED10.44.P$K LED10.45.P$K LED10.46.P$K LED10.47.P$K LED10.48.P$K LED10.49.P$K LED10.50.P$K LED10.51.P$K LED10.52.P$K LED10.53.P$K LED10.54.P$K LED10.55.P$K LED10.56.P$K LED10.57.P$K LED10.58.P$K LED10.59.P$K LED10.60.P$K LED10.61.P$K LED10.62.P$K LED10.63.P$K Y.10.P$
N$Y.11: LED11.0.P$K LED11.1.P$K LED11.2.P$K LED11.3.P$K LED11.4.P$K LED11.5.P$K LED11.6.P$K LED11.7.P$K LED11.8.P$K LED11.9.P$K LED11.10.P$K LED11.11.P$K LED11.12.P$K LED11.13.P$K LED11.14.P$K LED11.15.P$K LED11.16.P$K LED11.17.P$K LED11.18.P$K LED11.19.P$K LED11.20.P$K LED11.21.P$K LED11.22.P$K LED11.23.P$K LED11.24.P$K LED11.25.P$K LED11.26.P$K LED11.27.P$K LED11.28.P$K LED11.29.P$K LED11.30.P$K LED11.31.P$K LED11.32.P$K LED11.33.P$K LED11.34.P$K LED11.35.P$K LED11.36.P$K LED11.37.P$K LED11.38.P$K LED11.39.P$K LED11.40.P$K LED11.41.P$K LED11.42.P$K LED11.43.P$K LED11.44.P$K LED11.45.P$K LED11.46.P$K LED11.47.P$K LED11.48.P$K LED11.49.P$K LED11.50.P$K LED11.51.P$K LED11.52.P$K LED11.53.P$K LED11.54.P$K LED11.55.P$K LED11.56.P$K LED11.57.P$K LED11.58.P$K LED11.59.P$K LED11.60.P$K LED11.61.P$K LED11.62.P$K LED11.63.P$K Y.11.P$
N$Y.12: LED12.0.P$K LED12.1.P$K LED12.2.P$K LED12.3.P$K LED12.4.P$K LED12.5.P$K LED12.6.P$K LED12.7.P$K LED12.8.P$K LED12.9.P$K LED12.10.P$K LED12.11.P$K LED12.12.P$K LED12.13.P$K LED12.14.P$K LED12.15.P$K LED12.16.P$K LED12.17.P$K LED12.18.P$K LED12.19.P$K LED12.20.P$K LED12.21.P$K LED12.22.P$K LED12.23.P$K LED12.24.P$K LED12.25.P$K LED12.26.P$K LED12.27.P$K LED12.28.P$K LED12.29.P$K LED12.30.P$K LED12.31.P$K LED12.32.P$K LED12.33.P$K LED12.34.P$K LED12.35.P$K LED12.36.P$K LED12.37.P$K LED12.38.P$K LED12.39.P$K LED12.40.P$K LED12.41.P$K LED12.42.P$K LED12.43.P$K LED12.44.P$K LED12.45.P$K LED12.46.P$K LED12.47.P$K LED12.48.P$K LED12.49.P$K LED12.50.P$K LED12.51.P$K LED12.52.P$K LED12.53.P$K LED12.54.P$K LED12.55.P$K LED12.56.P$K LED12.57.P$K LED12.58.P$K LED12.59.P$K LED12.60.P$K LED12.61.P$K LED12.62.P$K LED12.63.P$K Y.12.P$
N$Y.13: LED13.0.P$K LED13.1.P$K LED13.2.P$K LED13.3.P$K LED13.4.P$K LED13.5.P$K LED13.6.P$K LED13.7.P$K LED13.8.P$K LED13.9.P$K LED13.10.P$K LED13.11.P$K LED13.12.P$K LED13.13.P$K LED13.14.P$K LED13.15.P$K LED13.16.P$K LED13.17.P$K LED13.18.P$K LED13.19.P$K LED13.20.P$K LED13.21.P$K LED13.22.P$K LED13.23.P$K LED13.24.P$K LED13.25.P$K LED13.26.P$K LED13.27.P$K LED13.28.P$K LED13.29.P$K LED13.30.P$K LED13.31.P$K LED13.32.P$K LED13.33.P$K LED13.34.P$K LED13.35.P$K LED13.36.P$K LED13.37.P$K LED13.38.P$K LED13.39.P$K LED13.40.P$K LED13.41.P$K LED13.42.P$K LED13.43.P$K LED13.44.P$K LED13.45.P$K LED13.46.P$K LED13.47.P$K LED13.48.P$K LED13.49.P$K LED13.50.P$K LED13.51.P$K LED13.52.P$K LED13.53.P$K LED13.54.P$K LED13.55.P$K LED13.56.P$K LED13.57.P$K LED13.58.P$K LED13.59.P$K LED13.60.P$K LED13.61.P$K LED13.62.P$K LED13.63.P$K Y.13.P$
N$Y.14: LED14.0.P$K LED14.1.P$K LED14.2.P$K LED14.3.P$K LED14.4.P$K LED14.5.P$K LED14.6.P$K LED14.7.P$K LED14.8.P$K LED14.9.P$K LED14.10.P$K LED14.11.P$K LED14.12.P$K LED14.13.P$K LED14.14.P$K LED14.15.P$K LED14.16.P$K LED14.17.P$K LED14.18.P$K LED14.19.P$K LED14.20.P$K LED14.21.P$K LED14.22.P$K LED14.23.P$K LED14.24.P$K LED14.25.P$K LED14.26.P$K LED14.27.P$K LED14.28.P$K LED14.29.P$K LED14.30.P$K LED14.31.P$K LED14.32.P$K LED14.33.P$K LED14.34.P$K LED14.35.P$K LED14.36.P$K LED14.37.P$K LED14.38.P$K LED14.39.P$K LED14.40.P$K LED14.41.P$K LED14.42.P$K LED14.43.P$K LED14.44.P$K LED14.45.P$K LED14.46.P$K LED14.47.P$K LED14.48.P$K LED14.49.P$K LED14.50.P$K LED14.51.P$K LED14.52.P$K LED14.53.P$K LED14.54.P$K LED14.55.P$K LED14.56.P$K LED14.57.P$K LED14.58.P$K LED14.59.P$K LED14.60.P$K LED14.61.P$K LED14.62.P$K LED14.63.P$K Y.14.P$
N$Y.15: LED15.0.P$K LED15.1.P$K LED15.2.P$K LED15.3.P$K LED15.4.P$K LED15.5.P$K LED15.6.P$K LED15.7.P$K LED15.8.P$K LED15.9.P$K LED15.10.P$K LED15.11.P$K LED15.12.P$K LED15.13.P$K LED15.14.P$K LED15.15.P$K LED15.16.P$K LED15.17.P$K LED15.18.P$K LED15.19.P$K LED15.20.P$K LED15.21.P$K LED15.22.P$K LED15.23.P$K LED15.24.P$K LED15.25.P$K LED15.26.P$K LED15.27.P$K LED15.28.P$K LED15.29.P$K LED15.30.P$K LED15.31.P$K LED15.32.P$K LED15.33.P$K LED15.34.P$K LED15.35.P$K LED15.36.P$K LED15.37.P$K LED15.38.P$K LED15.39.P$K LED15.40.P$K LED15.41.P$K LED15.42.P$K LED15.43.P$K LED15.44.P$K LED15.45.P$K LED15.46.P$K LED15.47.P$K LED15.48.P$K LED15.49.P$K LED15.50.P$K LED15.51.P$K LED15.52.P$K LED15.53.P$K LED15.54.P$K LED15.55.P$K LED15.56.P$K LED15.57.P$K LED15.58.P$K LED15.59.P$K LED15.60.P$K LED15.61.P$K LED15.62.P$K LED15.63.P$K Y.15.P$
N$Y.16: LED16.0.P$K LED16.1.P$K LED16.2.P$K LED16.3.P$K LED16.4.P$K LED16.5.P$K LED16.6.P$K LED16.7.P$K LED16.8.P$K LED16.9.P$K LED16.10.P$K LED16.11.P$K LED16.12.P$K LED16.13.P$K LED16.14.P$K LED16.15.P$K LED16.16.P$K LED16.17.P$K LED16.18.P$K LED16.19.P$K LED16.20.P$K LED16.21.P$K LED16.22.P$K LED16.23.P$K LED16.24.P$K LED16.25.P$K LED16.26.P$K LED16.27.P$K LED16.28.P$K LED16.29.P$K LED16.30.P$K LED16.31.P$K LED16.32.P$K LED16.33.P$K LED16.34.P$K LED16.35.P$K LED16.36.P$K LED16.37.P$K LED16.38.P$K LED16.39.P$K LED16.40.P$K LED16.41.P$K LED16.42.P$K LED16.43.P$K LED16.44.P$K LED16.45.P$K LED16.46.P$K LED16.47.P$K LED16.48.P$K LED16.49.P$K LED16.50.P$K LED16.51.P$K LED16.52.P$K LED16.53.P$K LED16.54.P$K LED16.55.P$K LED16.56.P$K LED16.57.P$K LED16.58.P$K LED16.59.P$K LED16.60.P$K LED16.61.P$K LED16.62.P$K LED16.63.P$K Y.16.P$
N$Y.17: LED17.0.P$K LED17.1.P$K LED17.2.P$K LED17.3.P$K LED17.4.P$K LED17.5.P$K LED17.6.P$K LED17.7.P$K LED17.8.P$K LED17.9.P$K LED17.10.P$K LED17.11.P$K LED17.12.P$K LED17.13.P$K LED17.14.P$K LED17.15.P$K LED17.16.P$K LED17.17.P$K LED17.18.P$K LED17.19.P$K LED17.20.P$K LED17.21.P$K LED17.22.P$K LED17.23.P$K LED17.24.P$K LED17.25.P$K LED17.26.P$K LED17.27.P$K LED17.28.P$K LED17.29.P$K LED17.30.P$K LED17.31.P$K LED17.32.P$K LED17.33.P$K LED17.34.P$K LED17.35.P$K LED17.36.P$K LED17.37.P$K LED17.38.P$K LED17.39.P$K LED17.40.P$K LED17.41.P$K LED17.42.P$K LED17.43.P$K LED17.44.P$K LED17.45.P$K LED17.46.P$K LED17.47.P$K LED17.48.P$K LED17.49.P$K LED17.50.P$K LED17.51.P$K LED17.52.P$K LED17.53.P$K LED17.54.P$K LED17.55.P$K LED17.56.P$K LED17.57.P$K LED17.58.P$K LED17.59.P$K LED17.60.P$K LED17.61.P$K LED17.62.P$K LED17.63.P$K Y.17.P$
N$Y.18: LED18.0.P$K LED18.1.P$K LED18.2.P$K LED18.3.P$K LED18.4.P$K LED18.5.P$K LED18.6.P$K LED18.7.P$K LED18.8.P$K LED18.9.P$K LED18.10.P$K LED18.11.P$K LED18.12.P$K LED18.13.P$K LED18.14.P$K LED18.15.P$K LED18.16.P$K LED18.17.P$K LED18.18.P$K LED18.19.P$K LED18.20.P$K LED18.21.P$K LED18.22.P$K LED18.23.P$K LED18.24.P$K LED18.25.P$K LED18.26.P$K LED18.27.P$K LED18.28.P$K LED18.29.P$K LED18.30.P$K LED18.31.P$K LED18.32.P$K LED18.33.P$K LED18.34.P$K LED18.35.P$K LED18.36.P$K LED18.37.P$K LED18.38.P$K LED18.39.P$K LED18.40.P$K LED18.41.P$K LED18.42.P$K LED18.43.P$K LED18.44.P$K LED18.45.P$K LED18.46.P$K LED18.47.P$K LED18.48.P$K LED18.49.P$K LED18.50.P$K LED18.51.P$K LED18.52.P$K LED18.53.P$K LED18.54.P$K LED18.55.P$K LED18.56.P$K LED18.57.P$K LED18.58.P$K LED18.59.P$K LED18.60.P$K LED18.61.P$K LED18.62.P$K LED18.63.P$K Y.18.P$
N$Y.19: LED19.0.P$K LED19.1.P$K LED19.2.P$K LED19.3.P$K LED19.4.P$K LED19.5.P$K LED19.6.P$K LED19.7.P$K LED19.8.P$K LED19.9.P$K LED19.10.P$K LED19.11.P$K LED19.12.P$K LED19.13.P$K LED19.14.P$K LED19.15.P$K LED19.16.P$K LED19.17.P$K LED19.18.P$K LED19.19.P$K LED19.20.P$K LED19.21.P$K LED19.22.P$K LED19.23.P$K LED19.24.P$K LED19.25.P$K LED19.26.P$K LED19.27.P$K LED19.28.P$K LED19.29.P$K LED19.30.P$K LED19.31.P$K LED19.32.P$K LED19.33.P$K LED19.34.P$K LED19.35.P$K LED19.36.P$K LED19.37.P$K LED19.38.P$K LED19.39.P$K LED19.40.P$K LED19.41.P$K LED19.42.P$K LED19.43.P$K LED19.44.P$K LED19.45.P$K LED19.46.P$K LED19.47.P$K LED19.48.P$K LED19.49.P$K LED19.50.P$K LED19.51.P$K LED19.52.P$K LED19.53.P$K LED19.54.P$K LED19.55.P$K LED19.56.P$K LED19.57.P$K LED19.58.P$K LED19.59.P$K LED19.60.P$K LED19.61.P$K LED19.62.P$K LED19.63.P$K Y.19.P$
N$Y.20: LED20.0.P$K LED20.1.P$K LED20.2.P$K LED20.3.P$K LED20.4.P$K LED20.5.P$K LED20.6.P$K LED20.7.P$K LED20.8.P$K LED20.9.P$K LED20.10.P$K LED20.11.P$K LED20.12.P$K LED20.13.P$K LED20.14.P$K LED20.15.P$K LED20.16.P$K LED20.17.P$K LED20.18.P$K LED20.19.P$K LED20.20.P$K LED20.21.P$K LED20.22.P$K LED20.23.P$K LED20.24.P$K LED20.25.P$K LED20.26.P$K LED20.27.P$K LED20.28.P$K LED20.29.P$K LED20.30.P$K LED20.31.P$K LED20.32.P$K LED20.33.P$K LED20.34.P$K LED20.35.P$K LED20.36.P$K LED20.37.P$K LED20.38.P$K LED20.39.P$K LED20.40.P$K LED20.41.P$K LED20.42.P$K LED20.43.P$K LED20.44.P$K LED20.45.P$K LED20.46.P$K LED20.47.P$K LED20.48.P$K LED20.49.P$K LED20.50.P$K LED20.51.P$K LED20.52.P$K LED20.53.P$K LED20.54.P$K LED20.55.P$K LED20.56.P$K LED20.57.P$K LED20.58.P$K LED20.59.P$K LED20.60.P$K LED20.61.P$K LED20.62.P$K LED20.63.P$K Y.20.P$
N$Y.21: LED21.0.P$K LED21.1.P$K LED21.2.P$K LED21.3.P$K LED21.4.P$K LED21.5.P$K LED21.6.P$K LED21.7.P$K LED21.8.P$K LED21.9.P$K LED21.10.P$K LED21.11.P$K LED21.12.P$K LED21.13.P$K LED21.14.P$K LED21.15.P$K LED21.16.P$K LED21.17.P$K LED21.18.P$K LED21.19.P$K LED21.20.P$K LED21.21.P$K LED21.22.P$K LED21.23.P$K LED21.24.P$K LED21.25.P$K LED21.26.P$K LED21.27.P$K LED21.28.P$K LED21.29.P$K LED21.30.P$K LED21.31.P$K LED21.32.P$K LED21.33.P$K LED21.34.P$K LED21.35.P$K LED21.36.P$K LED21.37.P$K LED21.38.P$K LED21.39.P$K LED21.40.P$K LED21.41.P$K LED21.42.P$K LED21.43.P$K LED21.44.P$K LED21.45.P$K LED21.46.P$K LED21.47.P$K LED21.48.P$K LED21.49.P$K LED21.50.P$K LED21.51.P$K LED21.52.P$K LED21.53.P$K LED21.54.P$K LED21.55.P$K LED21.56.P$K LED21.57.P$K LED21.58.P$K LED21.59.P$K LED21.60.P$K LED21.61.P$K LED21.62.P$K LED21.63.P$K Y.21.P$

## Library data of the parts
LED0.0 LED0.1-LED0.63 LED1.0 LED1.1-LED1.63 LED2.0 LED2.1-LED2.63 LED3.0 LED3.1-LED3.63 LED4.0 LED4.1-LED4.63 LED5.0 LED5.1-LED5.63 LED6.0 LED6.1-LED6.63 LED7.0 LED7.1-LED7.63 LED8.0 LED8.1-LED8.63 LED9.0 LED9.1-LED9.63 LED10.0 LED10.1-LED10.63 LED11.0 LED11.1-LED11.63 LED12.0 LED12.1-LED12.63 LED13.0 LED13.1-LED13.63 LED14.0 LED14.1-LED14.63 LED15.0 LED15.1-LED15.63 LED16.0 LED16.1-LED16.63 LED17.0 LED17.1-LED17.63 LED18.0 LED18.1-LED18.63 LED19.0 LED19.1-LED19.63 LED20.0 LED20.1-LED20.63 LED21.0 LED21.1-LED21.63 = miniled:LED_CROSS
X0 X1-X63 Y.0 Y.1-Y.21 = Devs:PAD_PIN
